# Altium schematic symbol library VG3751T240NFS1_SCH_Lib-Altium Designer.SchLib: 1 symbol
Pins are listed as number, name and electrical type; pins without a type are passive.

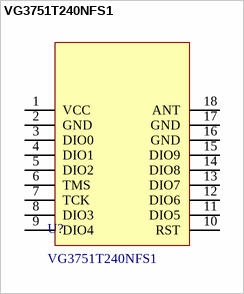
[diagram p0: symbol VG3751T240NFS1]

## VG3751T240NFS1
designator U?
VG3751T240NFS1 CC2640R2
footprint G3751NS1
footprint G3751NS1-TO
pins: 1 VCC, 2 GND, 3 DIO0, 4 DIO1, 5 DIO2, 6 TMS, 7 TCK, 8 DIO3, 9 DIO4, 10 RST, 11 DIO5, 12 DIO6, 13 DIO7, 14 DIO8, 15 DIO9, 16 GND, 17 GND, 18 ANT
